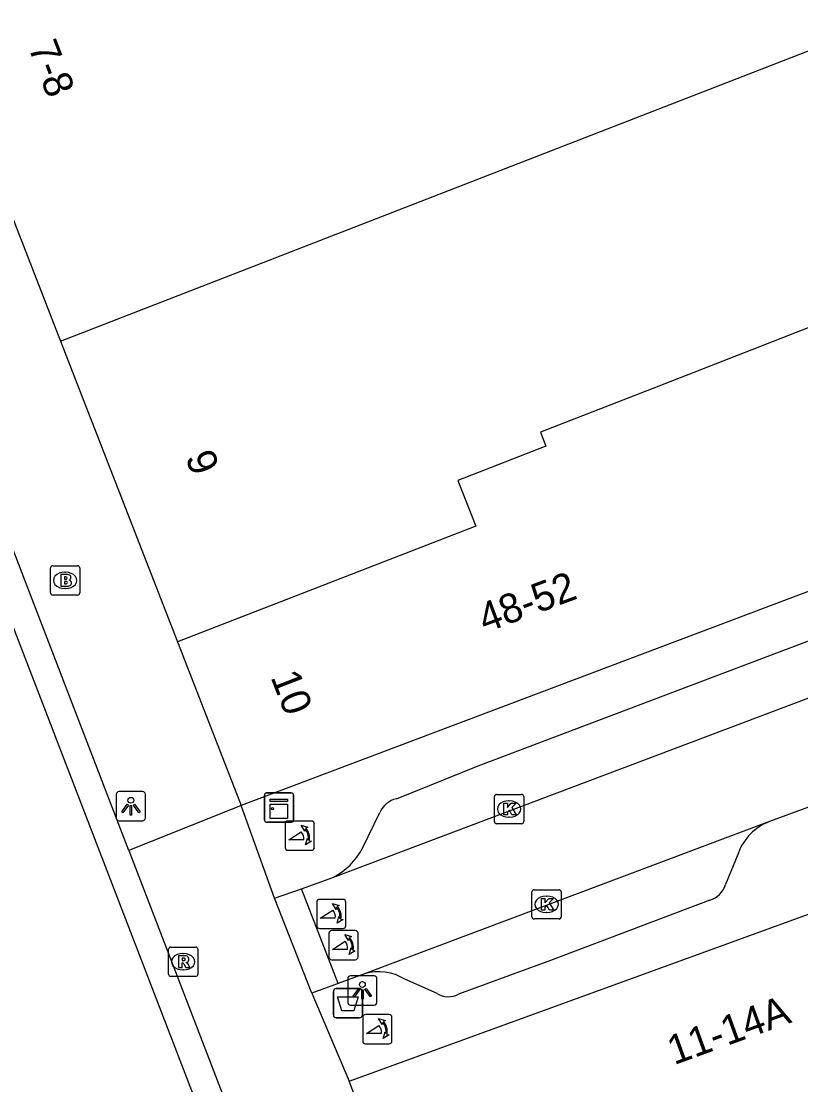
# Model space of a CAD drawing. Extents: x 160861 to 161308, y 384024 to 384878.
# Drawn here: x 160918.08 to 160944.7, y 384674.42 to 384710.74 of the extents above; entities that cross this region are included whole.
import ezdxf

# ---------------------------------------------------------------- set-up
doc = ezdxf.new("R2010")
doc.units = 0
for name, color, linetype in [('IMGEO_Afvalbak', 7, 'Continuous'), ('IMGEO_Brandkraan', 7, 'Continuous'), ('IMGEO_Fietspad_gesloten', 7, 'Continuous'), ('IMGEO_Fietspad_open', 7, 'Continuous'), ('IMGEO_Kast', 7, 'Continuous'), ('IMGEO_Kolk', 7, 'Continuous'), ('IMGEO_Lichtpunt', 7, 'Continuous'), ('IMGEO_Pand', 7, 'Continuous'), ('IMGEO_Pand_nummerreeks', 7, 'Continuous'), ('IMGEO_Poller', 7, 'Continuous'), ('IMGEO_Rijbaan_lokaal_open', 7, 'Continuous'), ('IMGEO_Rioolput', 7, 'Continuous'), ('IMGEO_Voetpad_open', 7, 'Continuous')]:
    doc.layers.add(name, color=color, linetype=linetype)

msp = doc.modelspace()

# ---------------------------------------------------------------- linework, layer by layer
at = {"layer": 'IMGEO_Afvalbak'}
for p, q in [((160928.736, 384676.803), (160928.736, 384677.603)), ((160928.736, 384677.603), (160928.736, 384676.803)), ((160928.836, 384677.703), (160929.626, 384677.703)), ((160929.626, 384677.703), (160928.836, 384677.703)), ((160929.726, 384677.603), (160929.726, 384676.803)), ((160929.726, 384676.803), (160929.726, 384677.603)), ((160929.626, 384676.703), (160928.836, 384676.703)), ((160928.836, 384676.703), (160929.626, 384676.703))]:
    msp.add_line(p, q, dxfattribs=at)
msp.add_lwpolyline([(160928.879, 384677.417), (160929.583, 384677.417), (160929.434, 384676.947), (160929.028, 384676.947), (160928.879, 384677.417)], dxfattribs=at)
for centre, start, end in [((160928.836, 384677.603), 90, 180), ((160928.836, 384677.603), 90, 180), ((160929.626, 384677.603), 0, 90), ((160929.626, 384677.603), 360, 90), ((160928.836, 384676.803), 180, 270), ((160928.836, 384676.803), 180, 270), ((160929.626, 384676.803), 270, 0), ((160929.626, 384676.803), 270, 0)]:
    msp.add_arc(centre, 0.1, start, end, dxfattribs=at)
at = {"layer": 'IMGEO_Brandkraan'}
for p, q in [((160919.075, 384691.219), (160919.075, 384692.071)), ((160919.15, 384692.145), (160920.002, 384692.145)), ((160919.563, 384691.925), (160919.588, 384691.925)), ((160920.076, 384692.071), (160920.076, 384691.219)), ((160919.586, 384691.365), (160919.561, 384691.365)), ((160920.002, 384691.145), (160919.15, 384691.145))]:
    msp.add_line(p, q, dxfattribs=at)
for points in [[(160919.075, 384691.219), (160919.075, 384692.071)], [(160919.15, 384692.145), (160920.002, 384692.145)], [(160920.076, 384692.071), (160920.076, 384691.219)], [(160919.423, 384691.845), (160919.423, 384691.445), (160919.636, 384691.445)], [(160919.654, 384691.845), (160919.423, 384691.845)], [(160919.602, 384691.764), (160919.548, 384691.764), (160919.548, 384691.688)], [(160919.548, 384691.688), (160919.601, 384691.688)], [(160919.61, 384691.612), (160919.548, 384691.612), (160919.548, 384691.531)], [(160919.548, 384691.531), (160919.61, 384691.531)], [(160920.002, 384691.145), (160919.15, 384691.145)]]:
    msp.add_lwpolyline(points, dxfattribs=at)
for centre, radius, start, end in [((160919.152, 384692.069), 0.0765, 91.552, 178.448), ((160919.152, 384692.069), 0.0765, 91.552, 178.448), ((160920, 384692.069), 0.0765, 1.552, 88.448), ((160920, 384692.069), 0.0765, 1.552, 88.448), ((160919.603, 384691.726), 0.0379, 267.8285, 90.9355), ((160919.611, 384691.571), 0.0404, 269.8759, 90.5077), ((160919.658, 384691.7), 0.145, 59.4692, 91.5367), ((160919.683, 384691.747), 0.0922, 285.5137, 58.1501), ((160919.688, 384691.555), 0.105, 301.3115, 78.989), ((160919.152, 384691.221), 0.0765, 181.552, 268.448), ((160919.152, 384691.221), 0.0765, 181.552, 268.448), ((160919.642, 384691.696), 0.251, 268.6676, 293.5347), ((160920, 384691.221), 0.0765, 271.552, 358.448), ((160920, 384691.221), 0.0765, 271.552, 358.448)]:
    msp.add_arc(centre, radius, start, end, dxfattribs=at)
for centre, major_axis, ratio, start_param, end_param in [((160919.562, 384691.645), (-0.387, 0.002), 0.722429, 4.712389, 7.853982), ((160919.587, 384691.645), (-0.39, 0.002), 0.717154, 1.570796, 4.712389)]:
    msp.add_ellipse(centre, major_axis=major_axis, ratio=ratio, start_param=start_param, end_param=end_param, dxfattribs=at)
at = {"layer": 'IMGEO_Fietspad_gesloten'}
msp.add_lwpolyline([(160952.428, 384599.868), (160937.604, 384638.593), (160892.484, 384755.839)], dxfattribs=at)
at = {"layer": 'IMGEO_Fietspad_open'}
for points in [[(160921.747, 384682.423), (160893.385, 384756.183)], [(160921.747, 384682.423), (160931.483, 384657.104)]]:
    msp.add_lwpolyline(points, dxfattribs=at)
at = {"layer": 'IMGEO_Kast'}
for p, q in [((160926.379, 384683.46), (160926.379, 384684.301)), ((160926.379, 384684.301), (160926.379, 384683.46)), ((160926.454, 384684.385), (160927.295, 384684.385)), ((160927.295, 384684.385), (160926.454, 384684.385)), ((160927.379, 384684.31), (160927.379, 384683.469)), ((160927.379, 384683.469), (160927.379, 384684.31)), ((160927.304, 384683.385), (160926.463, 384683.385)), ((160926.463, 384683.385), (160927.304, 384683.385))]:
    msp.add_line(p, q, dxfattribs=at)
for points in [[(160926.574, 384684.175), (160927.174, 384684.175), (160927.174, 384684.09), (160926.574, 384684.09), (160926.574, 384684.175)], [(160926.574, 384684), (160927.174, 384684), (160927.174, 384683.511), (160926.574, 384683.511), (160926.574, 384684)]]:
    msp.add_lwpolyline(points, dxfattribs=at)
msp.add_circle((160926.658, 384683.849), 0.0377, dxfattribs=at)
for centre, start, end in [((160926.457, 384684.307), 92.4484, 184.2845), ((160926.457, 384684.307), 92.4484, 184.2845), ((160927.301, 384684.307), 2.4484, 94.2845), ((160927.301, 384684.307), 2.4484, 94.2845), ((160926.457, 384683.463), 182.4484, 274.2845), ((160926.457, 384683.463), 182.4484, 274.2845), ((160927.301, 384683.463), 272.4484, 4.2845), ((160927.301, 384683.463), 272.4484, 4.2845)]:
    msp.add_arc(centre, 0.0779, start, end, dxfattribs=at)
at = {"layer": 'IMGEO_Kolk'}
for p, q in [((160934.312, 384684.334), (160935.164, 384684.334)), ((160934.237, 384683.408), (160934.237, 384684.26)), ((160934.725, 384684.114), (160934.75, 384684.114)), ((160935.238, 384684.26), (160935.238, 384683.408)), ((160934.748, 384683.554), (160934.723, 384683.554)), ((160935.164, 384683.334), (160934.312, 384683.334)), ((160935.518, 384680.153), (160935.518, 384681.005)), ((160935.593, 384681.079), (160936.445, 384681.079)), ((160936.519, 384681.005), (160936.519, 384680.153)), ((160936.006, 384680.859), (160936.031, 384680.859)), ((160936.029, 384680.299), (160936.004, 384680.299)), ((160936.445, 384680.079), (160935.593, 384680.079))]:
    msp.add_line(p, q, dxfattribs=at)
for points in [[(160934.312, 384684.334), (160935.164, 384684.334)], [(160934.237, 384683.408), (160934.237, 384684.26)], [(160934.558, 384684.034), (160934.681, 384684.034), (160934.681, 384683.883), (160934.811, 384684.034), (160934.975, 384684.034), (160934.829, 384683.883), (160934.982, 384683.634), (160934.83, 384683.634), (160934.745, 384683.798), (160934.681, 384683.731), (160934.681, 384683.634), (160934.558, 384683.634), (160934.558, 384684.034)], [(160935.238, 384684.26), (160935.238, 384683.408)], [(160935.164, 384683.334), (160934.312, 384683.334)], [(160935.518, 384680.153), (160935.518, 384681.005)], [(160935.593, 384681.079), (160936.445, 384681.079)], [(160936.519, 384681.005), (160936.519, 384680.153)], [(160935.839, 384680.779), (160935.962, 384680.779), (160935.962, 384680.628), (160936.092, 384680.779), (160936.256, 384680.779), (160936.11, 384680.628), (160936.263, 384680.379), (160936.111, 384680.379), (160936.026, 384680.543), (160935.962, 384680.476), (160935.962, 384680.379), (160935.839, 384680.379), (160935.839, 384680.779)], [(160936.445, 384680.079), (160935.593, 384680.079)]]:
    msp.add_lwpolyline(points, dxfattribs=at)
for centre, start, end in [((160934.314, 384684.258), 91.552, 178.448), ((160934.314, 384684.258), 91.552, 178.448), ((160935.162, 384684.258), 1.552, 88.448), ((160935.162, 384684.258), 1.552, 88.448), ((160934.314, 384683.41), 181.552, 268.448), ((160934.314, 384683.41), 181.552, 268.448), ((160935.162, 384683.41), 271.552, 358.448), ((160935.162, 384683.41), 271.552, 358.448), ((160935.595, 384681.003), 91.552, 178.448), ((160935.595, 384681.003), 91.552, 178.448), ((160936.443, 384681.003), 1.552, 88.448), ((160936.443, 384681.003), 1.552, 88.448), ((160935.595, 384680.155), 181.552, 268.448), ((160935.595, 384680.155), 181.552, 268.448), ((160936.443, 384680.155), 271.552, 358.448), ((160936.443, 384680.155), 271.552, 358.448)]:
    msp.add_arc(centre, 0.0765, start, end, dxfattribs=at)
for centre, major_axis, ratio, start_param, end_param in [((160934.724, 384683.834), (-0.387, 0.002), 0.722429, 4.712389, 7.853982), ((160934.749, 384683.834), (-0.39, 0.002), 0.717154, 1.570796, 4.712389), ((160936.005, 384680.579), (-0.387, 0.002), 0.722429, 4.712389, 7.853982), ((160936.03, 384680.579), (-0.39, 0.002), 0.717154, 1.570796, 4.712389)]:
    msp.add_ellipse(centre, major_axis=major_axis, ratio=ratio, start_param=start_param, end_param=end_param, dxfattribs=at)
at = {"layer": 'IMGEO_Lichtpunt'}
for p, q in [((160921.322, 384684.336), (160921.322, 384683.529)), ((160921.322, 384684.336), (160921.322, 384683.529)), ((160922.224, 384684.431), (160921.416, 384684.431)), ((160922.224, 384684.431), (160921.416, 384684.431)), ((160922.318, 384683.529), (160922.318, 384684.336)), ((160922.318, 384683.529), (160922.318, 384684.336)), ((160921.416, 384683.435), (160922.224, 384683.435)), ((160921.416, 384683.435), (160922.224, 384683.435)), ((160930.13, 384678.137), (160929.322, 384678.137)), ((160930.13, 384678.137), (160929.322, 384678.137)), ((160929.228, 384678.042), (160929.228, 384677.235)), ((160929.228, 384678.042), (160929.228, 384677.235)), ((160930.224, 384677.235), (160930.224, 384678.042)), ((160930.224, 384677.235), (160930.224, 384678.042)), ((160929.322, 384677.141), (160930.13, 384677.141)), ((160929.322, 384677.141), (160930.13, 384677.141))]:
    msp.add_line(p, q, dxfattribs=at)
for points in [[(160921.696, 384684), (160921.735, 384683.972), (160921.547, 384683.71), (160921.509, 384683.737), (160921.696, 384684)], [(160921.798, 384683.952), (160921.845, 384683.952), (160921.845, 384683.63), (160921.798, 384683.63), (160921.798, 384683.952)], [(160921.908, 384683.972), (160921.946, 384683.999), (160922.133, 384683.737), (160922.094, 384683.709), (160921.908, 384683.972)], [(160929.602, 384677.706), (160929.641, 384677.678), (160929.453, 384677.416), (160929.415, 384677.443), (160929.602, 384677.706)], [(160929.704, 384677.658), (160929.751, 384677.658), (160929.751, 384677.336), (160929.704, 384677.336), (160929.704, 384677.658)], [(160929.814, 384677.678), (160929.852, 384677.705), (160930.039, 384677.443), (160930, 384677.415), (160929.814, 384677.678)]]:
    msp.add_lwpolyline(points, dxfattribs=at)
for centre in [(160921.821, 384684.134), (160929.727, 384677.84)]:
    msp.add_circle(centre, 0.0994, dxfattribs=at)
for centre, start, end in [((160921.416, 384684.336), 90, 180), ((160921.416, 384684.336), 90, 180), ((160922.224, 384684.336), 0, 90), ((160922.224, 384684.336), 0, 90), ((160921.416, 384683.529), 180, 270), ((160921.416, 384683.529), 180, 270), ((160922.224, 384683.529), 270, 0), ((160922.224, 384683.529), 270, 360), ((160929.322, 384678.042), 90, 180), ((160929.322, 384678.042), 90, 180), ((160930.13, 384678.042), 0, 90), ((160930.13, 384678.042), 0, 90), ((160929.322, 384677.235), 180, 270), ((160929.322, 384677.235), 180, 270), ((160930.13, 384677.235), 270, 0), ((160930.13, 384677.235), 270, 360)]:
    msp.add_arc(centre, 0.0946, start, end, dxfattribs=at)
at = {"layer": 'IMGEO_Pand'}
for points in [[(160913.229, 384715.759), (160919.422, 384699.819)], [(160919.422, 384699.819), (160956.01, 384714.035)], [(160945.27, 384700.396), (160940.055, 384698.364), (160935.806, 384696.709), (160935.994, 384696.225), (160932.991, 384695.058), (160933.596, 384693.502), (160923.413, 384689.547)], [(160919.422, 384699.819), (160919.502, 384699.614), (160923.413, 384689.547)], [(160948.331, 384692.54), (160925.586, 384683.954)], [(160923.413, 384689.547), (160925.586, 384683.954)], [(160929.276, 384674.544), (160954.733, 384683.794), (160955.307, 384684.002), (160957.27, 384684.595)], [(160933.47, 384663.572), (160929.276, 384674.544)]]:
    msp.add_lwpolyline(points, dxfattribs=at)
at = {"layer": 'IMGEO_Poller'}
for p, q in [((160927.089, 384683.328), (160927.089, 384682.521)), ((160927.089, 384683.328), (160927.089, 384682.521)), ((160927.991, 384683.423), (160927.183, 384683.423)), ((160927.991, 384683.423), (160927.183, 384683.423)), ((160928.085, 384682.521), (160928.085, 384683.328)), ((160928.085, 384682.521), (160928.085, 384683.328)), ((160927.183, 384682.426), (160927.991, 384682.426)), ((160927.183, 384682.426), (160927.991, 384682.426)), ((160928.166, 384680.655), (160928.166, 384679.848)), ((160928.166, 384680.655), (160928.166, 384679.848)), ((160929.068, 384680.75), (160928.26, 384680.75)), ((160929.068, 384680.75), (160928.26, 384680.75)), ((160929.162, 384679.848), (160929.162, 384680.655)), ((160929.162, 384679.848), (160929.162, 384680.655)), ((160928.26, 384679.753), (160929.068, 384679.753)), ((160928.26, 384679.753), (160929.068, 384679.753)), ((160928.583, 384679.59), (160928.583, 384678.783)), ((160928.583, 384679.59), (160928.583, 384678.783)), ((160929.485, 384679.685), (160928.677, 384679.685)), ((160929.485, 384679.685), (160928.677, 384679.685)), ((160929.579, 384678.783), (160929.579, 384679.59)), ((160929.579, 384678.783), (160929.579, 384679.59)), ((160928.677, 384678.688), (160929.485, 384678.688)), ((160928.677, 384678.688), (160929.485, 384678.688)), ((160929.74, 384676.72), (160929.74, 384675.913)), ((160929.74, 384676.72), (160929.74, 384675.913)), ((160930.642, 384676.815), (160929.834, 384676.815)), ((160930.642, 384676.815), (160929.834, 384676.815)), ((160930.736, 384675.913), (160930.736, 384676.72)), ((160930.736, 384675.913), (160930.736, 384676.72)), ((160929.834, 384675.818), (160930.642, 384675.818)), ((160929.834, 384675.818), (160930.642, 384675.818))]:
    msp.add_line(p, q, dxfattribs=at)
for points in [[(160927.768, 384683.152), (160927.756, 384683.079), (160927.631, 384683.284)], [(160927.631, 384683.284), (160927.862, 384683.218), (160927.791, 384683.186)], [(160927.724, 384682.779), (160927.211, 384682.779), (160927.641, 384683.054)], [(160927.784, 384682.607), (160927.85, 384682.838), (160927.88, 384682.77)], [(160927.916, 384682.743), (160927.988, 384682.732), (160927.784, 384682.607)], [(160928.801, 384680.106), (160928.288, 384680.106), (160928.718, 384680.381)], [(160928.845, 384680.479), (160928.833, 384680.406), (160928.708, 384680.611)], [(160928.708, 384680.611), (160928.939, 384680.545), (160928.868, 384680.513)], [(160928.861, 384679.934), (160928.927, 384680.165), (160928.957, 384680.097)], [(160928.993, 384680.07), (160929.065, 384680.059), (160928.861, 384679.934)], [(160929.218, 384679.041), (160928.705, 384679.041), (160929.135, 384679.316)], [(160929.262, 384679.414), (160929.25, 384679.341), (160929.125, 384679.546)], [(160929.125, 384679.546), (160929.356, 384679.48), (160929.285, 384679.448)], [(160929.278, 384678.869), (160929.344, 384679.1), (160929.374, 384679.032)], [(160929.41, 384679.005), (160929.482, 384678.994), (160929.278, 384678.869)], [(160930.419, 384676.544), (160930.407, 384676.471), (160930.282, 384676.676)], [(160930.282, 384676.676), (160930.513, 384676.61), (160930.442, 384676.578)], [(160930.375, 384676.171), (160929.862, 384676.171), (160930.292, 384676.446)], [(160930.435, 384675.999), (160930.501, 384676.23), (160930.531, 384676.162)], [(160930.567, 384676.135), (160930.639, 384676.124), (160930.435, 384675.999)]]:
    msp.add_lwpolyline(points, dxfattribs=at)
for centre, radius, start, end in [((160927.183, 384683.328), 0.0946, 90, 180), ((160927.183, 384683.328), 0.0946, 90, 180), ((160927.41, 384682.839), 0.516, 349.3569, 42.2912), ((160927.991, 384683.328), 0.0946, 0, 90), ((160927.991, 384683.328), 0.0946, 0, 90), ((160927.396, 384682.829), 0.332, 351.3247, 42.4854), ((160927.41, 384682.839), 0.476, 351.7527, 41.1691), ((160927.183, 384682.521), 0.0946, 180, 270), ((160927.183, 384682.521), 0.0946, 180, 270), ((160927.991, 384682.521), 0.0946, 270, 0), ((160927.991, 384682.521), 0.0946, 270, 0), ((160928.26, 384680.655), 0.0946, 90, 180), ((160928.26, 384680.655), 0.0946, 90, 180), ((160929.068, 384680.655), 0.0946, 0, 90), ((160929.068, 384680.655), 0.0946, 0, 90), ((160928.473, 384680.156), 0.332, 351.3247, 42.4854), ((160928.487, 384680.166), 0.476, 351.7527, 41.1691), ((160928.487, 384680.166), 0.516, 349.3569, 42.2912), ((160928.26, 384679.848), 0.0946, 180, 270), ((160928.26, 384679.848), 0.0946, 180, 270), ((160928.677, 384679.59), 0.0946, 90, 180), ((160928.677, 384679.59), 0.0946, 90, 180), ((160929.068, 384679.848), 0.0946, 270, 0), ((160929.068, 384679.848), 0.0946, 270, 0), ((160929.485, 384679.59), 0.0946, 0, 90), ((160929.485, 384679.59), 0.0946, 0, 90), ((160928.89, 384679.091), 0.332, 351.3247, 42.4854), ((160928.904, 384679.101), 0.476, 351.7527, 41.1691), ((160928.904, 384679.101), 0.516, 349.3569, 42.2912), ((160928.677, 384678.783), 0.0946, 180, 270), ((160928.677, 384678.783), 0.0946, 180, 270), ((160929.485, 384678.783), 0.0946, 270, 0), ((160929.485, 384678.783), 0.0946, 270, 0), ((160929.834, 384676.72), 0.0946, 90, 180), ((160929.834, 384676.72), 0.0946, 90, 180), ((160930.642, 384676.72), 0.0946, 0, 90), ((160930.642, 384676.72), 0.0946, 0, 90), ((160930.047, 384676.221), 0.332, 351.3247, 42.4854), ((160930.061, 384676.231), 0.476, 351.7527, 41.1691), ((160930.061, 384676.231), 0.516, 349.3569, 42.2912), ((160929.834, 384675.913), 0.0946, 180, 270), ((160929.834, 384675.913), 0.0946, 180, 270), ((160930.642, 384675.913), 0.0946, 270, 0), ((160930.642, 384675.913), 0.0946, 270, 0)]:
    msp.add_arc(centre, radius, start, end, dxfattribs=at)
at = {"layer": 'IMGEO_Rijbaan_lokaal_open'}
for points in [[(160928.722, 384681.501), (160959.689, 384693.195)], [(160947.406, 384684.802), (160943.625, 384683.404)], [(160943.625, 384683.404), (160929.794, 384678.201)], [(160927.644, 384681.106), (160928.722, 384681.501)], [(160928.902, 384677.875), (160927.644, 384681.106)], [(160929.794, 384678.201), (160928.902, 384677.875)]]:
    msp.add_lwpolyline(points, dxfattribs=at)
at = {"layer": 'IMGEO_Rioolput'}
for p, q in [((160923.107, 384678.193), (160923.107, 384679.045)), ((160923.182, 384679.119), (160924.034, 384679.119)), ((160923.595, 384678.899), (160923.62, 384678.899)), ((160924.108, 384679.045), (160924.108, 384678.193)), ((160924.034, 384678.119), (160923.182, 384678.119)), ((160923.618, 384678.339), (160923.593, 384678.339))]:
    msp.add_line(p, q, dxfattribs=at)
for points in [[(160923.107, 384678.193), (160923.107, 384679.045)], [(160923.182, 384679.119), (160924.034, 384679.119)], [(160924.108, 384679.045), (160924.108, 384678.193)], [(160923.696, 384678.817), (160923.444, 384678.819), (160923.444, 384678.419)], [(160923.444, 384678.419), (160923.568, 384678.419), (160923.568, 384678.581), (160923.579, 384678.581)], [(160923.622, 384678.738), (160923.568, 384678.738), (160923.568, 384678.657)], [(160923.568, 384678.657), (160923.62, 384678.657)], [(160923.626, 384678.552), (160923.697, 384678.419), (160923.837, 384678.419), (160923.772, 384678.545)], [(160924.034, 384678.119), (160923.182, 384678.119)]]:
    msp.add_lwpolyline(points, dxfattribs=at)
for centre, radius, start, end in [((160923.184, 384679.043), 0.0765, 91.552, 178.448), ((160923.184, 384679.043), 0.0765, 91.552, 178.448), ((160924.032, 384679.043), 0.0765, 1.552, 88.448), ((160924.032, 384679.043), 0.0765, 1.552, 88.448), ((160923.578, 384678.528), 0.0533, 26.0293, 88.6989), ((160923.604, 384678.846), 0.19, 274.7715, 282.9687), ((160923.628, 384678.642), 0.0964, 77.0061, 93.1865), ((160923.642, 384678.699), 0.0378, 276.6634, 79.6772), ((160923.695, 384678.707), 0.109, 350.3612, 89.416), ((160923.693, 384678.707), 0.112, 277.5842, 350.9817), ((160923.677, 384678.492), 0.108, 29.5134, 73.7905), ((160923.184, 384678.195), 0.0765, 181.552, 268.448), ((160923.184, 384678.195), 0.0765, 181.552, 268.448), ((160924.032, 384678.195), 0.0765, 271.552, 358.448), ((160924.032, 384678.195), 0.0765, 271.552, 358.448)]:
    msp.add_arc(centre, radius, start, end, dxfattribs=at)
for centre, major_axis, ratio, start_param, end_param in [((160923.594, 384678.619), (-0.387, 0.002), 0.722429, 4.712389, 7.853982), ((160923.619, 384678.619), (-0.39, 0.002), 0.717154, 1.570796, 4.712389)]:
    msp.add_ellipse(centre, major_axis=major_axis, ratio=ratio, start_param=start_param, end_param=end_param, dxfattribs=at)
at = {"layer": 'IMGEO_Voetpad_open'}
for points in [[(160930.887, 384684.184), (160933.675, 384685.307), (160956.181, 384693.829)], [(160925.586, 384683.954), (160921.747, 384682.423)], [(160926.724, 384680.788), (160925.586, 384683.954)], [(160929.73, 384682.499), (160930.323, 384683.721)], [(160942.567, 384682.339), (160942.127, 384681.252)], [(160926.724, 384680.788), (160927.644, 384681.106)], [(160928.003, 384677.547), (160926.724, 384680.788)], [(160941.589, 384680.725), (160936.155, 384678.657), (160933.01, 384677.507)], [(160928.902, 384677.875), (160928.003, 384677.547)], [(160932.28, 384677.534), (160931.181, 384678.019)], [(160928.003, 384677.547), (160928.927, 384675.368), (160929.276, 384674.544)]]:
    msp.add_lwpolyline(points, dxfattribs=at)
for centre, radius, start, end in [((160931.062, 384683.395), 0.808, 102.5387, 156.2279), ((160944.281, 384681.694), 1.832, 110.9958, 159.382), ((160927.692, 384683.55), 2.293, 296.6986, 332.7301), ((160941.374, 384681.483), 0.788, 285.855, 342.9614), ((160930.293, 384676.626), 1.652, 57.4784, 107.5705), ((160932.668, 384678.155), 0.732, 237.9658, 297.7978)]:
    msp.add_arc(centre, radius, start, end, dxfattribs=at)

# ---------------------------------------------------------------- texts
at = {"layer": 'IMGEO_Pand_nummerreeks'}
for s, rotation, p in [('7-8', 291.1252, (160918.303, 384709.868)), ('9', 291.2336, (160923.667, 384695.852)), ('48-52', 20.4718, (160933.918, 384689.844)), ('10', 291.2336, (160926.583, 384688.345)), ('11-14A', 19.969, (160940.369, 384675.084))]:
    msp.add_text(s, height=1, rotation=rotation, dxfattribs=at).set_placement(p)

doc.saveas('drawing.dxf')
